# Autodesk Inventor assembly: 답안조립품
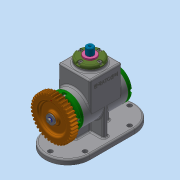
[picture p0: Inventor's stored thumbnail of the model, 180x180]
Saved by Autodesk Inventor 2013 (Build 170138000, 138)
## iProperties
Created: 2020-01
Part Number: 답안조립품
Document SubType Name: Assembly
Designer: Administrator
Author: Administrator
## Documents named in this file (18)
- C:\Users\Administrator\Desktop\600104V1009\답안조립품.iam
- C:\Users\Administrator\Desktop\600104V1009\본체.ipt
- C:\Users\Administrator\Desktop\600104V1009\가변스프링.ipt
- C:\Users\Administrator\Desktop\600104V1009\뒤커버.ipt
- C:\Users\Administrator\Desktop\600104V1009\멈춤링.ipt
- C:\Users\Administrator\Desktop\600104V1009\베어링 6203.ipt
- C:\Users\Administrator\Desktop\600104V1009\볼트 M4.ipt
- C:\Users\Administrator\Desktop\600104V1009\부시.ipt
- C:\Users\Administrator\Desktop\600104V1009\상부커버.ipt
- C:\Users\Administrator\Desktop\600104V1009\스퍼기어.ipt
- C:\Users\Administrator\Desktop\600104V1009\스프링와셔.ipt
- C:\Users\Administrator\Desktop\600104V1009\스프링조립용 와셔.ipt
- C:\Users\Administrator\Desktop\600104V1009\슬라이더.ipt
- C:\Users\Administrator\Desktop\600104V1009\앞커버.ipt
- C:\Users\Administrator\Desktop\600104V1009\오일 실 17 30 5.ipt
- C:\Users\Administrator\Desktop\600104V1009\키 4x4x12.ipt
- C:\Users\Administrator\Desktop\600104V1009\편심축.ipt
- C:\Users\Administrator\Desktop\600104V1009\평와셔.ipt
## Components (1 placed, 1 different names)
1. 가변스프링:1
